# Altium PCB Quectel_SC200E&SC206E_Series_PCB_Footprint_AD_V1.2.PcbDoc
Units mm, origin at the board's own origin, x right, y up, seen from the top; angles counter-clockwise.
Board outline 152.4 x 101.6 mm, 2 copper layers (Top Layer, Bottom Layer); 1 components, 0 nets, 274 pads, 0 vias.
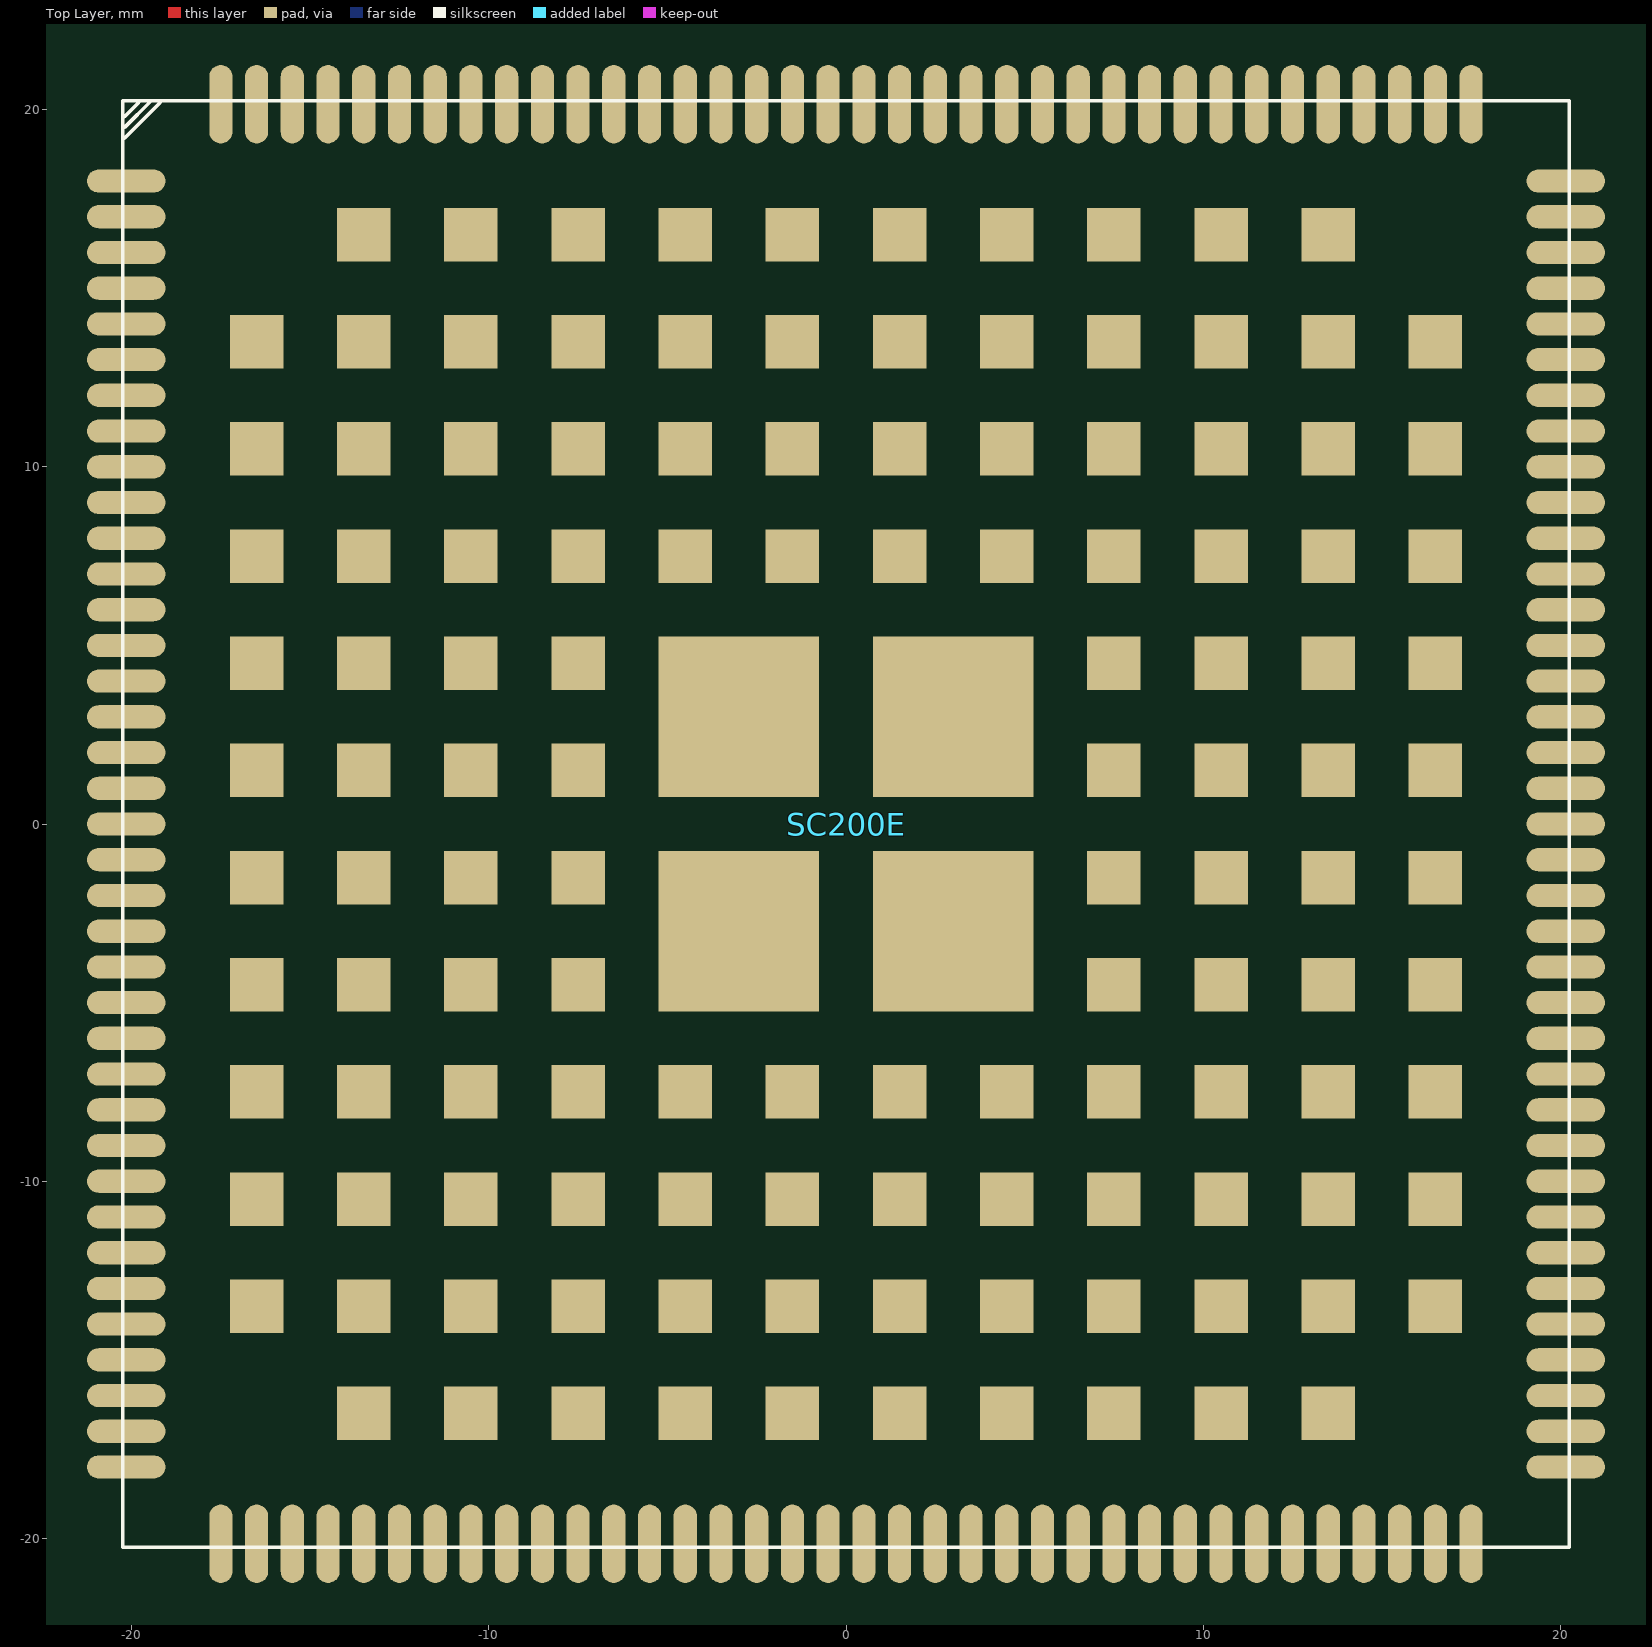
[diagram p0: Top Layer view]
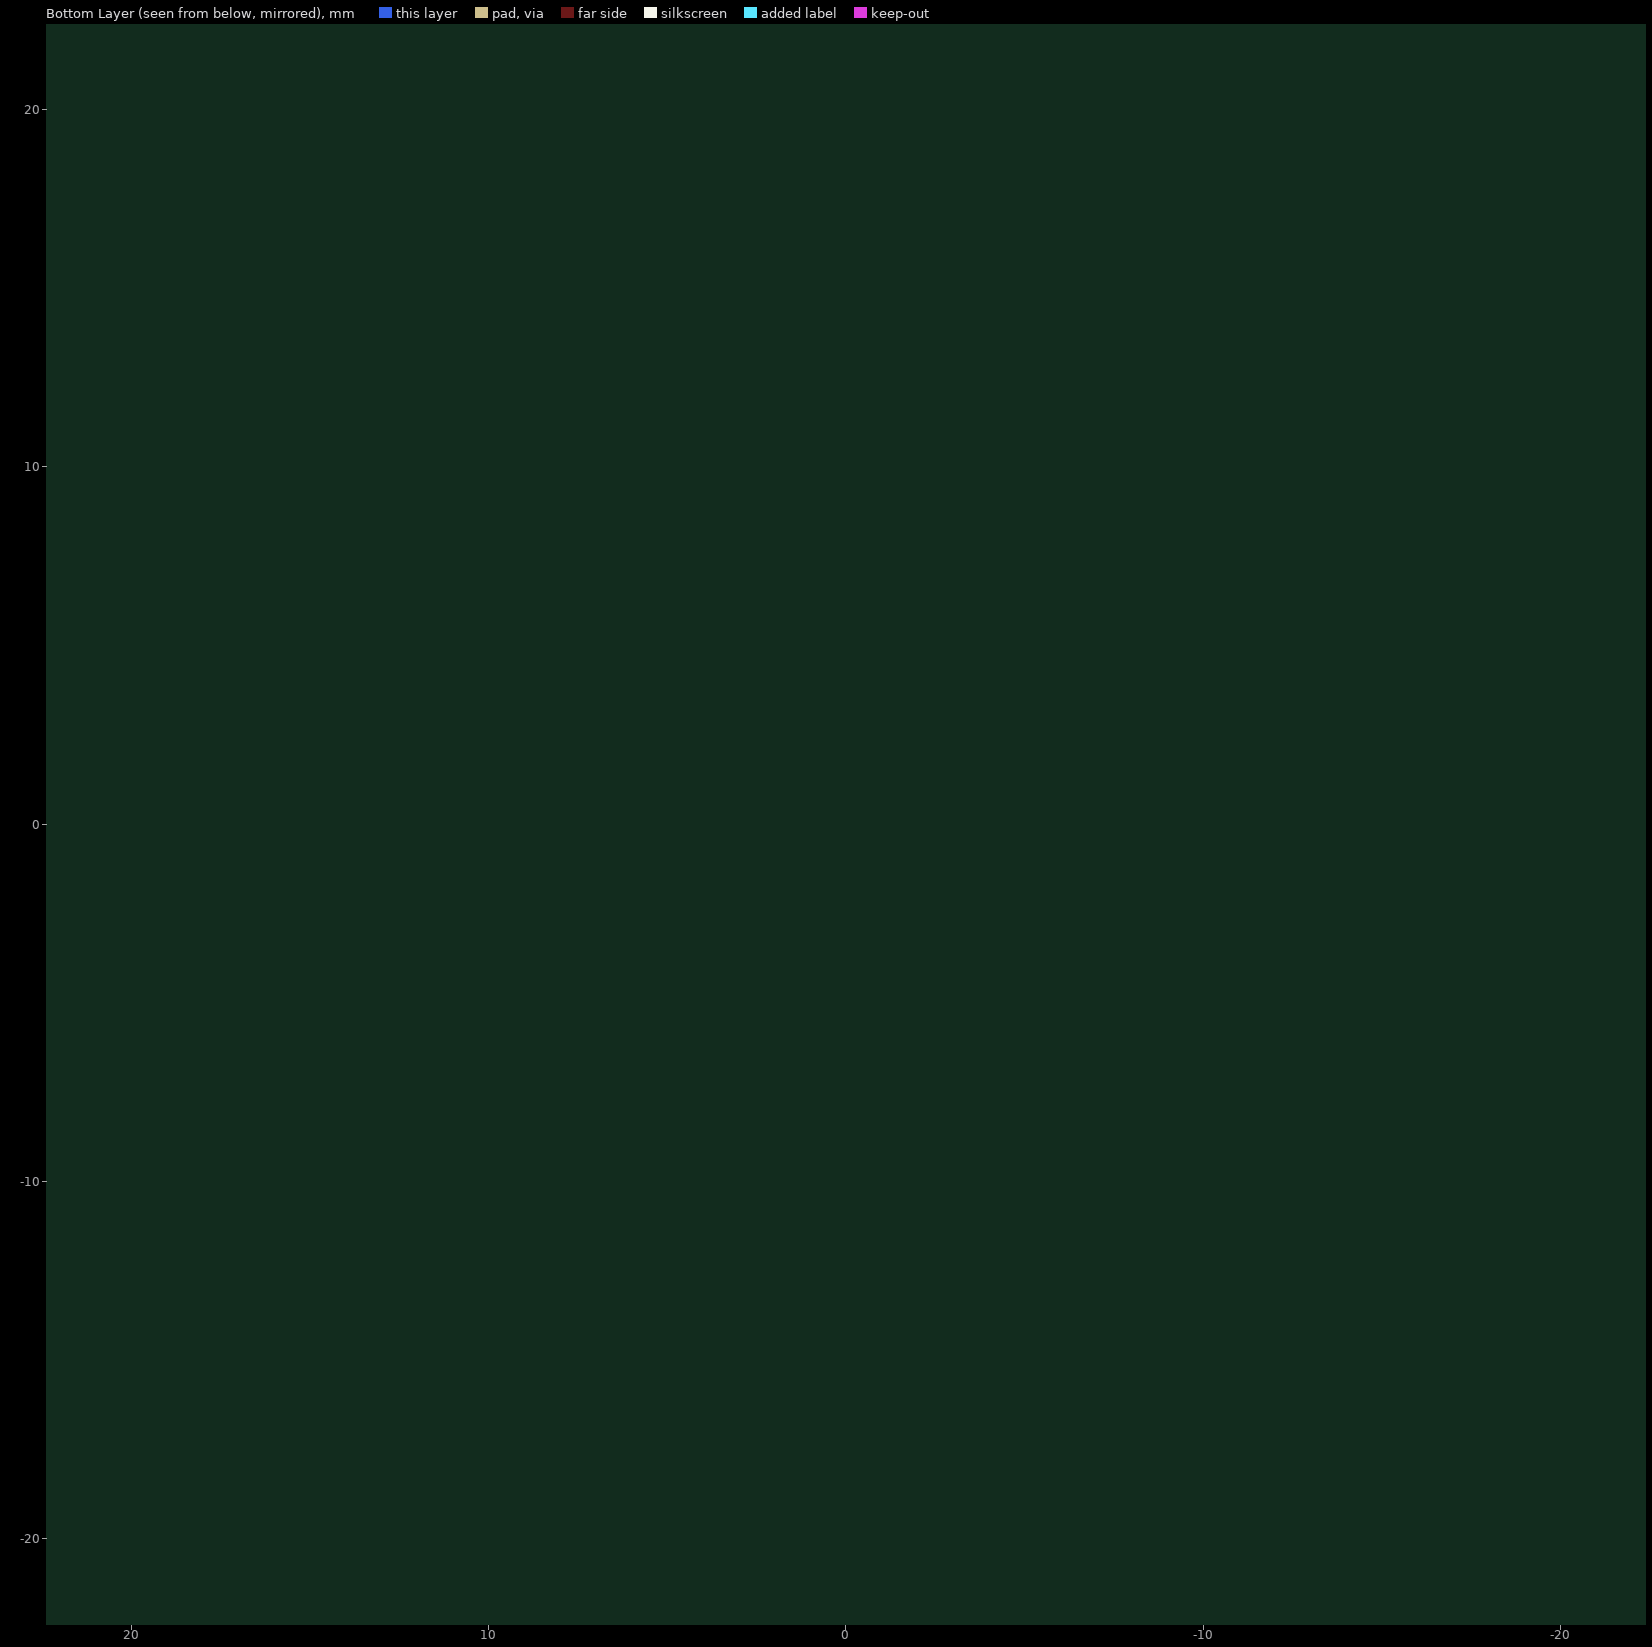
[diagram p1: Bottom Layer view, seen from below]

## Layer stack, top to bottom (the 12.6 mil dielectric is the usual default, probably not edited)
Top Solder: solder mask 0.0102, Solder Resist, Dk 3.5
Top Layer: signal copper 0.0356
Dielectric1: dielectric 0.32, FR-4, Dk 4.8
Bottom Layer: signal copper 0.0356
Bottom Solder: solder mask 0.0102, Solder Resist, Dk 3.5

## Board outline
-70.993,-51.054 81.407,-51.054 81.407,50.546 -70.993,50.546

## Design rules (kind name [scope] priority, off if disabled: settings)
Clearance [All] p1: gap=0.254
PolygonConnect [All] p1: connectstyle=Relief reliefconductorwidth=0.254 reliefentries=4 polygonreliefangle="90 Angle" airgapwidth=0.254
RoutingVias [All] p1: holewidth=0.711 width=1.27 viastyle="Through Hole" minholewidth=0.711 minwidth=1.27 maxholewidth=0.711 maxwidth=1.27
SolderMaskExpansion [All] p1: expansion=0.102
Width [All] p1: maxlimit=0.254 minlimit=0.254 preferedwidth=0.254
30 further rules are at their usual default settings.

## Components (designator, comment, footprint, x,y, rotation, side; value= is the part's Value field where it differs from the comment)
SC200E "Comment" SC200E 0,0 r0 top

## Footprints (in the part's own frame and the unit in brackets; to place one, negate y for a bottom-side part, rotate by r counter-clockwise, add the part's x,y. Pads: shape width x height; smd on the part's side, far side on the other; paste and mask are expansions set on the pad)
SC200E [mm] "SC200E Smart Module RO"
  oval 2.2x0.65 smd paste+0 mask+0.05: 1(-20.15,18) 2(-20.15,17) 3(-20.15,16) 4(-20.15,15) 5(-20.15,14) 6(-20.15,13) 7(-20.15,12) 8(-20.15,11) 9(-20.15,10) 10(-20.15,9) 11(-20.15,8) 12(-20.15,7) 13(-20.15,6) 14(-20.15,5) 15(-20.15,4) 16(-20.15,3) 17(-20.15,2) 18(-20.15,1) 19(-20.15,0) 20(-20.15,-1) 21(-20.15,-2) 22(-20.15,-3) 23(-20.15,-4) 24(-20.15,-5) 25(-20.15,-6) 26(-20.15,-7) 27(-20.15,-8) 28(-20.15,-9) 29(-20.15,-10) 30(-20.15,-11) 31(-20.15,-12) 32(-20.15,-13) 33(-20.15,-14) 34(-20.15,-15) 35(-20.15,-16) 36(-20.15,-17) 37(-20.15,-18) 74(20.15,-18) 75(20.15,-17) 76(20.15,-16) 77(20.15,-15) 78(20.15,-14) 79(20.15,-13) 80(20.15,-12) 81(20.15,-11) 82(20.15,-10) 83(20.15,-9) 84(20.15,-8) 85(20.15,-7) 86(20.15,-6) 87(20.15,-5) 88(20.15,-4) 89(20.15,-3) 90(20.15,-2) 91(20.15,-1) 92(20.15,0) 93(20.15,1) 94(20.15,2) 95(20.15,3) 96(20.15,4) 97(20.15,5) 98(20.15,6) 99(20.15,7) 100(20.15,8) 101(20.15,9) 102(20.15,10) 103(20.15,11) 104(20.15,12) 105(20.15,13) 106(20.15,14) 107(20.15,15) 108(20.15,16) 109(20.15,17) 110(20.15,18)
  oval 0.65x2.2 smd paste+0 mask+0.05: 38(-17.5,-20.15) 39(-16.5,-20.15) 40(-15.5,-20.15) 41(-14.5,-20.15) 42(-13.5,-20.15) 43(-12.5,-20.15) 44(-11.5,-20.15) 45(-10.5,-20.15) 46(-9.5,-20.15) 47(-8.5,-20.15) 48(-7.5,-20.15) 49(-6.5,-20.15) 50(-5.5,-20.15) 51(-4.5,-20.15) 52(-3.5,-20.15) 53(-2.5,-20.15) 54(-1.5,-20.15) 55(-0.5,-20.15) 56(0.5,-20.15) 57(1.5,-20.15) 58(2.5,-20.15) 59(3.5,-20.15) 60(4.5,-20.15) 61(5.5,-20.15) 62(6.5,-20.15) 63(7.5,-20.15) 64(8.5,-20.15) 65(9.5,-20.15) 66(10.5,-20.15) 67(11.5,-20.15) 68(12.5,-20.15) 69(13.5,-20.15) 70(14.5,-20.15) 71(15.5,-20.15) 72(16.5,-20.15) 73(17.5,-20.15) 111(17.5,20.15) 112(16.5,20.15) 113(15.5,20.15) 114(14.5,20.15) 115(13.5,20.15) 116(12.5,20.15) 117(11.5,20.15) 118(10.5,20.15) 119(9.5,20.15) 120(8.5,20.15) 121(7.5,20.15) 122(6.5,20.15) 123(5.5,20.15) 124(4.5,20.15) 125(3.5,20.15) 126(2.5,20.15) 127(1.5,20.15) 128(0.5,20.15) 129(-0.5,20.15) 130(-1.5,20.15) 131(-2.5,20.15) 132(-3.5,20.15) 133(-4.5,20.15) 134(-5.5,20.15) 135(-6.5,20.15) 136(-7.5,20.15) 137(-8.5,20.15) 138(-9.5,20.15) 139(-10.5,20.15) 140(-11.5,20.15) 141(-12.5,20.15) 142(-13.5,20.15) 143(-14.5,20.15) 144(-15.5,20.15) 145(-16.5,20.15) 146(-17.5,20.15)
  rect 1.5x1.5 smd paste+0 mask+0.05: 147(-16.5,13.5) 148(-16.5,10.5) 149(-16.5,7.5) 150(-16.5,4.5) 151(-16.5,1.5) 152(-16.5,-1.5) 153(-16.5,-4.5) 154(-16.5,-7.5) 155(-16.5,-10.5) 156(-16.5,-13.5) 157(-13.5,-16.5) 158(-10.5,-16.5) 159(-7.5,-16.5) 160(-4.5,-16.5) 161(-1.5,-16.5) 162(1.5,-16.5) 163(4.5,-16.5) 164(7.5,-16.5) 165(10.5,-16.5) 166(13.5,-16.5) 167(16.5,-13.5) 168(16.5,-10.5) 169(16.5,-7.5) 170(16.5,-4.5) 171(16.5,-1.5) 172(16.5,1.5) 173(16.5,4.5) 174(16.5,7.5) 175(16.5,10.5) 176(16.5,13.5) 177(13.5,16.5) 178(10.5,16.5) 179(7.5,16.5) 180(4.5,16.5) 181(1.5,16.5) 182(-1.5,16.5) 183(-4.5,16.5) 184(-7.5,16.5) 185(-10.5,16.5) 186(-13.5,16.5) 187(-13.5,13.5) 188(-13.5,10.5) 189(-13.5,7.5) 190(-13.5,4.5) 191(-13.5,1.5) 192(-13.5,-1.5) 193(-13.5,-4.5) 194(-13.5,-7.5) 195(-13.5,-10.5) 196(-13.5,-13.5) 197(-10.5,-13.5) 198(-7.5,-13.5) 199(-4.5,-13.5) 200(-1.5,-13.5) 201(1.5,-13.5) 202(4.5,-13.5) 203(7.5,-13.5) 204(10.5,-13.5) 205(13.5,-13.5) 206(13.5,-10.5) 207(13.5,-7.5) 208(13.5,-4.5) 209(13.5,-1.5) 210(13.5,1.5) 211(13.5,4.5) 212(13.5,7.5) 213(13.5,10.5) 214(13.5,13.5) 215(10.5,13.5) 216(7.5,13.5) 217(4.5,13.5) 218(1.5,13.5) 219(-1.5,13.5) 220(-4.5,13.5) 221(-7.5,13.5) 222(-10.5,13.5) 223(-10.5,10.5) 224(-10.5,7.5) 225(-10.5,4.5) 226(-10.5,1.5) 227(-10.5,-1.5) 228(-10.5,-4.5) 229(-10.5,-7.5) 230(-10.5,-10.5) 231(-7.5,-10.5) 232(-4.5,-10.5) 233(-1.5,-10.5) 234(1.5,-10.5) 235(4.5,-10.5) 236(7.5,-10.5) 237(10.5,-10.5) 238(10.5,-7.5) 239(10.5,-4.5) 240(10.5,-1.5) 241(10.5,1.5) 242(10.5,4.5) 243(10.5,7.5) 244(10.5,10.5) 245(7.5,10.5) 246(4.5,10.5) 247(1.5,10.5) 248(-1.5,10.5) 249(-4.5,10.5) 250(-7.5,10.5) 251(-7.5,7.5) 252(-7.5,4.5) 253(-7.5,1.5) 254(-7.5,-1.5) 255(-7.5,-4.5) 256(-7.5,-7.5) 257(-4.5,-7.5) 258(-1.5,-7.5) 259(1.5,-7.5) 260(4.5,-7.5) 261(7.5,-7.5) 262(7.5,-4.5) 263(7.5,-1.5) 264(7.5,1.5) 265(7.5,4.5) 266(7.5,7.5) 267(4.5,7.5) 268(1.5,7.5) 269(-1.5,7.5) 270(-4.5,7.5)
  rect 4.5x4.5 smd paste-2.25 mask+0.05: 271(-3,3) 272(-3,-3) 273(3,-3) 274(3,3)
  silkscreen extent -20.25,-20.25 20.25,20.25

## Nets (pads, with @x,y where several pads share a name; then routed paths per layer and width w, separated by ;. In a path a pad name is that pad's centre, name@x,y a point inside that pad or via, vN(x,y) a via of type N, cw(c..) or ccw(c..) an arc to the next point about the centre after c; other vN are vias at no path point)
pads on no net: SC200E.1 SC200E.2 SC200E.3 SC200E.4 SC200E.5 SC200E.6 SC200E.7 SC200E.8 SC200E.9 SC200E.10 SC200E.11 SC200E.12 SC200E.13 SC200E.14 SC200E.15 SC200E.16 SC200E.17 SC200E.18 SC200E.19 SC200E.20 SC200E.21 SC200E.22 SC200E.23 SC200E.24 SC200E.25 SC200E.26 SC200E.27 SC200E.28 SC200E.29 SC200E.30 SC200E.31 SC200E.32 SC200E.33 SC200E.34 SC200E.35 SC200E.36 SC200E.37 SC200E.38 SC200E.39 SC200E.40 SC200E.41 SC200E.42 SC200E.43 SC200E.44 SC200E.45 SC200E.46 SC200E.47 SC200E.48 SC200E.49 SC200E.50 SC200E.51 SC200E.52 SC200E.53 SC200E.54 SC200E.55 SC200E.56 SC200E.57 SC200E.58 SC200E.59 SC200E.60 SC200E.61 SC200E.62 SC200E.63 SC200E.64 SC200E.65 SC200E.66 SC200E.67 SC200E.68 SC200E.69 SC200E.70 SC200E.71 SC200E.72 SC200E.73 SC200E.74 SC200E.75 SC200E.76 SC200E.77 SC200E.78 SC200E.79 SC200E.80 SC200E.81 SC200E.82 SC200E.83 SC200E.84 SC200E.85 SC200E.86 SC200E.87 SC200E.88 SC200E.89 SC200E.90 SC200E.91 SC200E.92 SC200E.93 SC200E.94 SC200E.95 SC200E.96 SC200E.97 SC200E.98 SC200E.99 SC200E.100 SC200E.101 SC200E.102 SC200E.103 SC200E.104 SC200E.105 SC200E.106 SC200E.107 SC200E.108 SC200E.109 SC200E.110 SC200E.111 SC200E.112 SC200E.113 SC200E.114 SC200E.115 SC200E.116 SC200E.117 SC200E.118 SC200E.119 SC200E.120 SC200E.121 SC200E.122 SC200E.123 SC200E.124 SC200E.125 SC200E.126 SC200E.127 SC200E.128 SC200E.129 SC200E.130 SC200E.131 SC200E.132 SC200E.133 SC200E.134 SC200E.135 SC200E.136 SC200E.137 SC200E.138 SC200E.139 SC200E.140 SC200E.141 SC200E.142 SC200E.143 SC200E.144 SC200E.145 SC200E.146 SC200E.147 SC200E.148 SC200E.149 SC200E.150 SC200E.151 SC200E.152 SC200E.153 SC200E.154 SC200E.155 SC200E.156 SC200E.157 SC200E.158 SC200E.159 SC200E.160 SC200E.161 SC200E.162 SC200E.163 SC200E.164 SC200E.165 SC200E.166 SC200E.167 SC200E.168 SC200E.169 SC200E.170 SC200E.171 SC200E.172 SC200E.173 SC200E.174 SC200E.175 SC200E.176 SC200E.177 SC200E.178 SC200E.179 SC200E.180 SC200E.181 SC200E.182 SC200E.183 SC200E.184 SC200E.185 SC200E.186 SC200E.187 SC200E.188 SC200E.189 SC200E.190 SC200E.191 SC200E.192 SC200E.193 SC200E.194 SC200E.195 SC200E.196 SC200E.197 SC200E.198 SC200E.199 SC200E.200 SC200E.201 SC200E.202 SC200E.203 SC200E.204 SC200E.205 SC200E.206 SC200E.207 SC200E.208 SC200E.209 SC200E.210 SC200E.211 SC200E.212 SC200E.213 SC200E.214 SC200E.215 SC200E.216 SC200E.217 SC200E.218 SC200E.219 SC200E.220 SC200E.221 SC200E.222 SC200E.223 SC200E.224 SC200E.225 SC200E.226 SC200E.227 SC200E.228 SC200E.229 SC200E.230 SC200E.231 SC200E.232 SC200E.233 SC200E.234 SC200E.235 SC200E.236 SC200E.237 SC200E.238 SC200E.239 SC200E.240 SC200E.241 SC200E.242 SC200E.243 SC200E.244 SC200E.245 SC200E.246 SC200E.247 SC200E.248 SC200E.249 SC200E.250 SC200E.251 SC200E.252 SC200E.253 SC200E.254 SC200E.255 SC200E.256 SC200E.257 SC200E.258 SC200E.259 SC200E.260 SC200E.261 SC200E.262 SC200E.263 SC200E.264 SC200E.265 SC200E.266 SC200E.267 SC200E.268 SC200E.269 SC200E.270 SC200E.271 SC200E.272 SC200E.273 SC200E.274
